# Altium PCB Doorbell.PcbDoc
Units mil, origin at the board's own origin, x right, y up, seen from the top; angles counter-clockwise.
Board outline 4807.09 x 4625.98 mil, 2 copper layers (Top Layer, Top, Bottom Layer, Bottom); 7 components, 5 nets, 25 pads, 0 vias.
Unrouted connection lines stored in the file: 2.
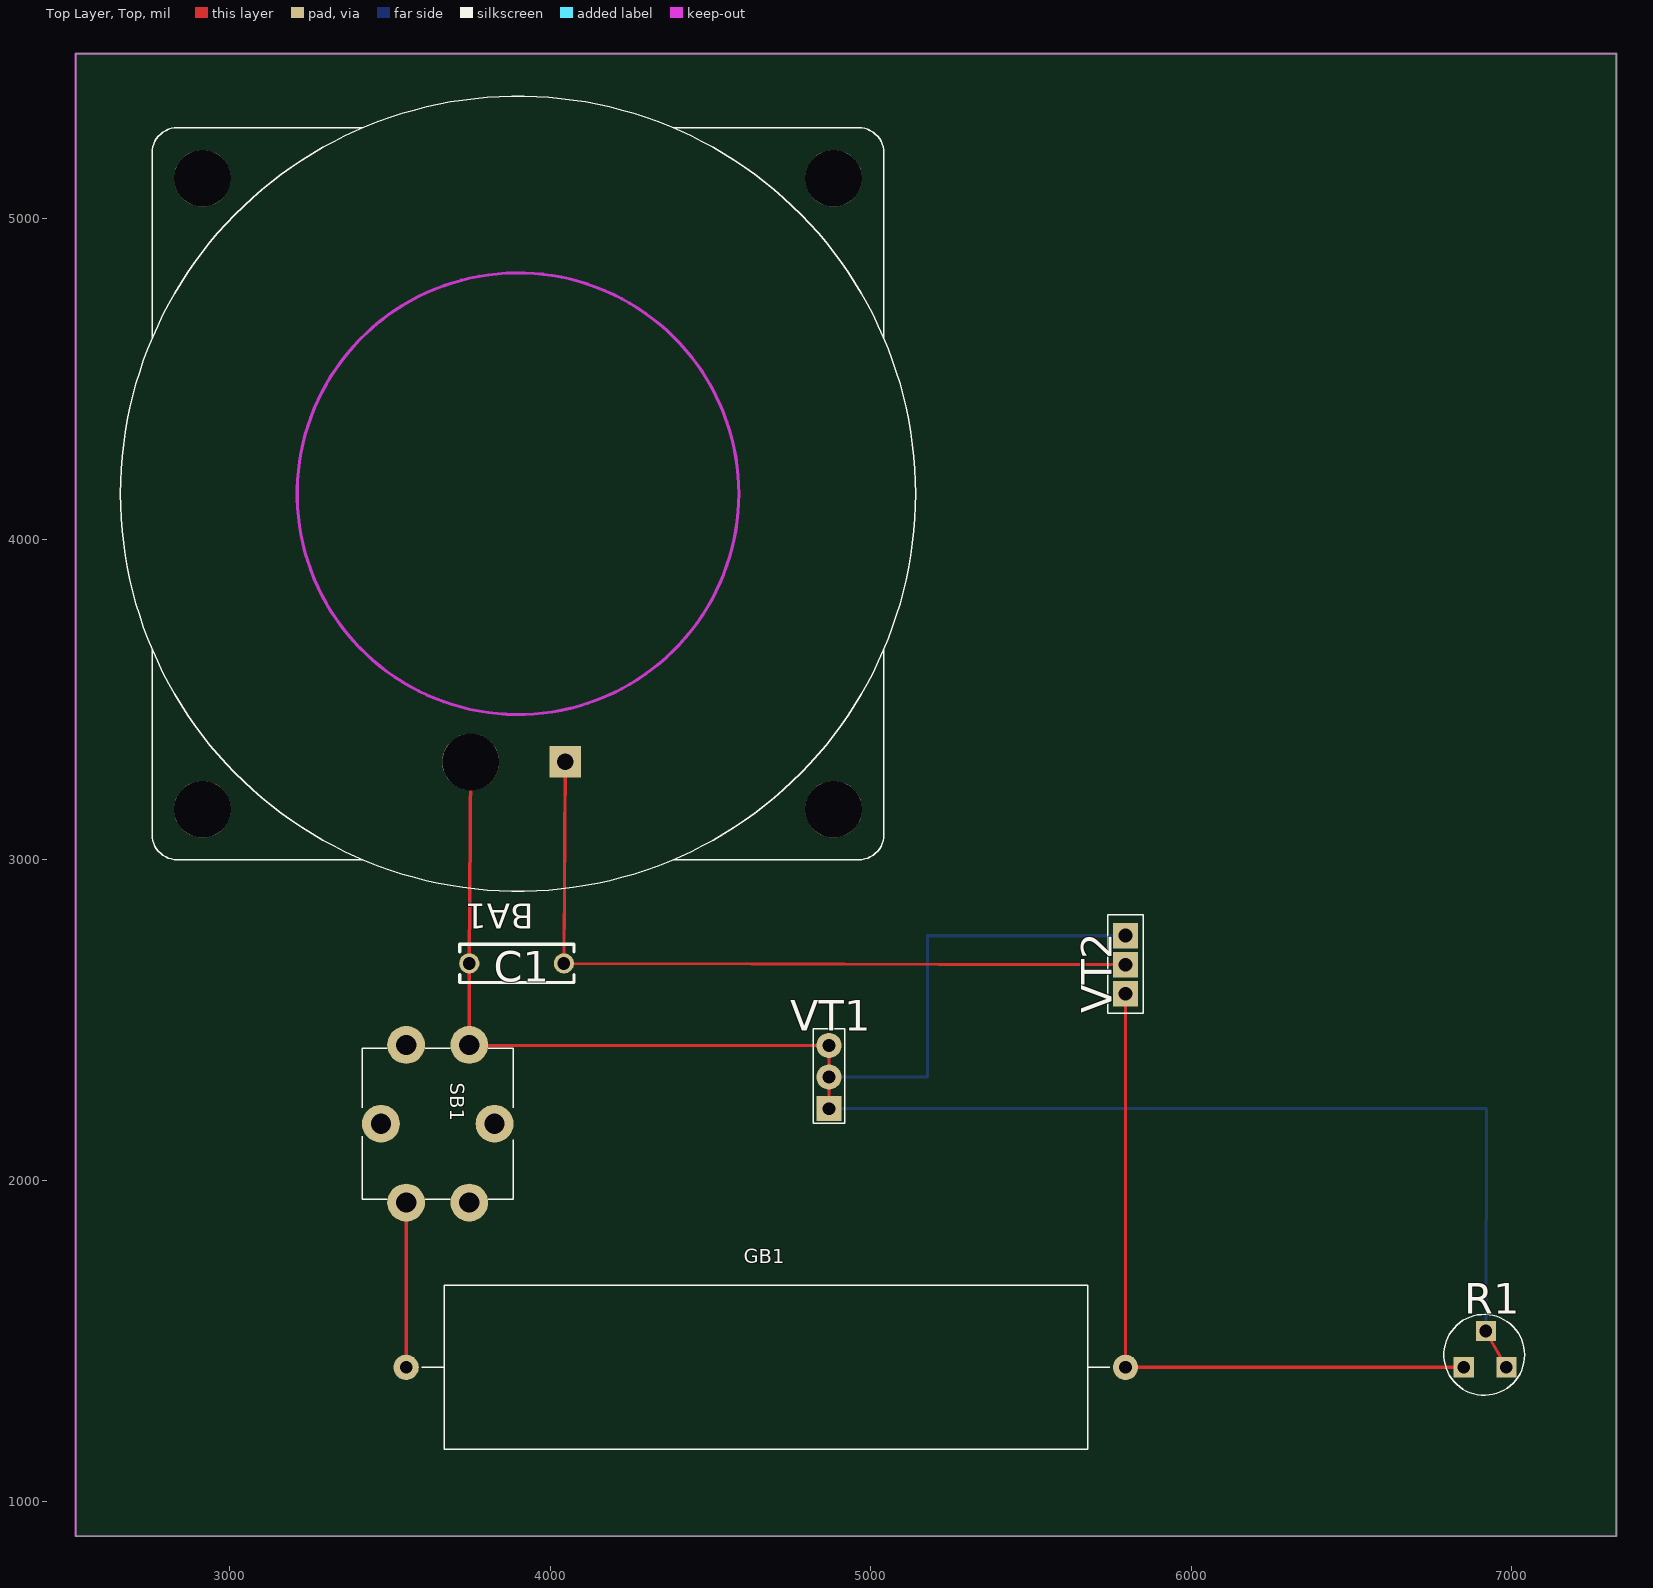
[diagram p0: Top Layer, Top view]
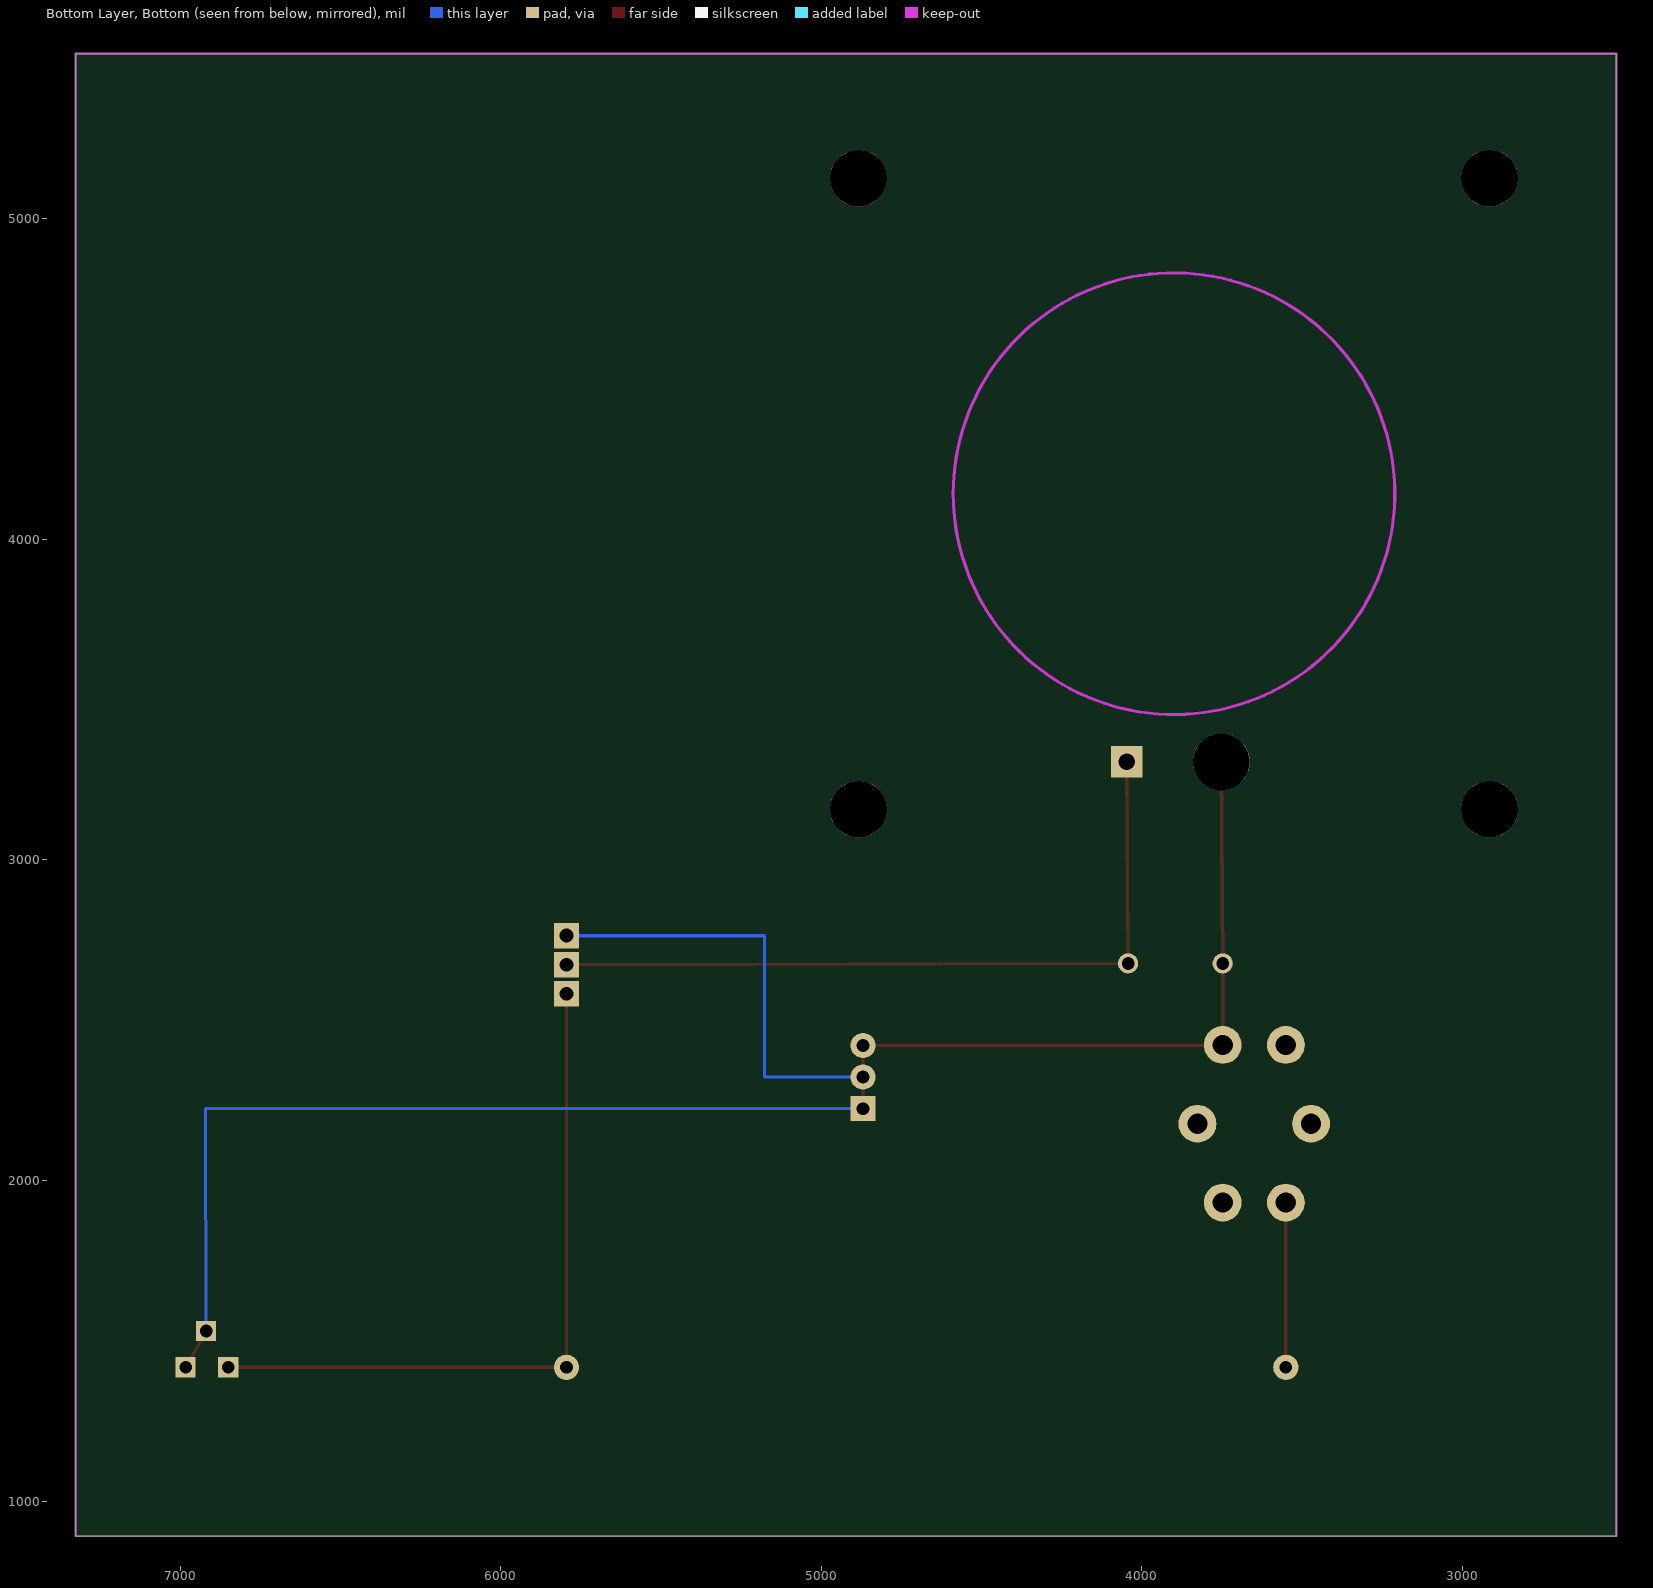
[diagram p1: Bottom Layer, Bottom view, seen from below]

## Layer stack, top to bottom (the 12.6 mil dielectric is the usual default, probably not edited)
Top Solder, Top Mask: solder mask 0.4, Solder Resist, Dk 3.5
Top Layer, Top: signal copper 1.4
Dielectric 1: dielectric 12.6, FR-4, Dk 4.8
Bottom Layer, Bottom: signal copper 1.4
Bottom Solder, Bot Mask: solder mask 0.4, Solder Resist, Dk 3.5

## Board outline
2519.68,5515.75 2519.68,889.76 7326.77,889.76 7326.77,5515.75

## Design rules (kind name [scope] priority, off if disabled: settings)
Clearance [All] p1: gap=10 ignorepadtopadclearanceinfootprint=FALSE except(0: Arc-Hole Track-Hole SMDPad-Hole THPad-Hole Via-Hole Fill-Hole Poly-Hole Region-Hole Text-Hole; 11.81: Arc-Arc Arc-Track Arc-THPad Arc-Via Track-Track Track-THPad Track-Via THPad-THPad THPad-Via Via-Via)
PlaneClearance [All] p1: clearance=10
PolygonConnect [All] p1: connectstyle=Relief reliefconductorwidth=10 reliefentries=4 polygonreliefangle="90 Angle" airgapwidth=10
RoutingVias [All] p1: holewidth=28 width=50 viastyle="Through Hole" minholewidth=28 minwidth=50 maxholewidth=28 maxwidth=50
SolderMaskExpansion [All] p1: expansion=4 istentingtop=FALSE
Width [All] p1: maxlimit=10 minlimit=10 preferedwidth=10
29 further rules are at their usual default settings.

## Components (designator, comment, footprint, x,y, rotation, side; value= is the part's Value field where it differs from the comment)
BA1 "" 0,25ГД-10 3900,4142.52 r180 top
C1 "0,01mk" K1017-2 3748.03,2677.17 r0 top
GB1 "" "BH-624 (1X AAA)" 4673.23,1417.32 r0 top
R1 "100K" SP3-19A1 6850.39,1417.32 r0 top
SB1 "" KAN1210-0731B 3649.61,2177.17 r270 top
VT1 "" KT13_КТ315Г(Primary) 4870.08,2224.41 r0 top
VT2 "" KT-27_Primary 5795.28,2582.68 r90 top

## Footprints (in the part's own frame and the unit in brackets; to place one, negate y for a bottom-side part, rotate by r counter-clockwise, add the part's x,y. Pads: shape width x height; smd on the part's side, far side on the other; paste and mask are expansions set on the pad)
0,25ГД-10 [mm]
  rect 2.5x2.5 hole 1.3: 1(-3.75,21.25)
  round 4.5 hole 4.5: 2(3.75,21.25) 3(-25,25) 4(25,25) 5(25,-25) 6(-25,-25)
  Keep-Out Layer, Board circle w0.25: c0,0 r17.5
  silkscreen extent -31.5,-31.5 31.5,31.5
"BH-624 (1X AAA)" [mm]
  round 2 hole 1: 1(-28.5,0) 2(28.5,0)
  silkscreen extent -27.25,-6.5 27.25,6.5
K1017-2 [mm]
  round 1.6 hole 1: 1(0,0) 2(7.5,0)
  silkscreen extent -0.76,-1.5 8.29,1.53
KAN1210-0731B [mm]
  round 3 hole 1.6: 1(-6.25,2.5) 2(6.25,2.5) 3(-6.25,-2.5) 4(6.25,-2.5) 5(0,4.5) 6(0,-4.5)
  silkscreen extent -6,-6 6,6
KT13_КТ315Г(Primary) [mm]
  rect 2x2 hole 1: 1(0,0)
  round 2 hole 1: 2(0,5) 3(0,2.5)
  silkscreen extent -1.25,-1.17 1.25,6.33
KT-27_Primary [mm]
  rect 2x2 hole 1.1: 1(0,0) 2(2.3,0) 3(4.6,0)
  silkscreen extent -1.56,-1.41 6.24,1.39
SP3-19A1 [mm]
  rect 1.6x1.6 hole 1: 1(0,0) 2(1.75,2.875) 3(3.375,0)
  silkscreen extent -1.57,-2.21 4.83,4.19

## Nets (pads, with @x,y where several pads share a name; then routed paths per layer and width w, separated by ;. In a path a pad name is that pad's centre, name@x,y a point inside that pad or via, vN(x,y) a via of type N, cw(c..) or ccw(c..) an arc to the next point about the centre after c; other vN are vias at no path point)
NET00000: GB1.1 SB1.3 SB1.4 | length 515.7
  Top Layer, Top w10: GB1.1 SB1.4 SB1.4@3551.18,1933.07
NET00001: BA1.2 C1.1 R1.2 R1.3 SB1.1 SB1.2 VT1.1 VT1.2 | length 5082.7
  Top Layer, Top w10: BA1.2 C1.1 SB1.1 3748.03,2421.26 VT1.2 VT1.1 ; R1.2 6917.32,1531.5 R1.3
  Bottom Layer, Bottom w10: VT1.1 6921.26,2224.41 R1.2
NET00004: BA1.1 C1.2 VT2.2 | length 2380.7
  Top Layer, Top w10: BA1.1 C1.2 VT2.2
NET00005: VT1.3 VT2.3 | length 1366.1
  Bottom Layer, Bottom w10: VT1.3 5177.17,2322.83 5177.17,2763.78 VT2.3
NET00007: GB1.2 R1.1 VT2.1 | length 2220.5
  Top Layer, Top w10: VT2.1 GB1.2 R1.1
pads on no net: BA1.3 BA1.4 BA1.5 BA1.6 SB1.5 SB1.6

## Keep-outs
Keep-Out Layer, Board:
  the board outline again, w5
